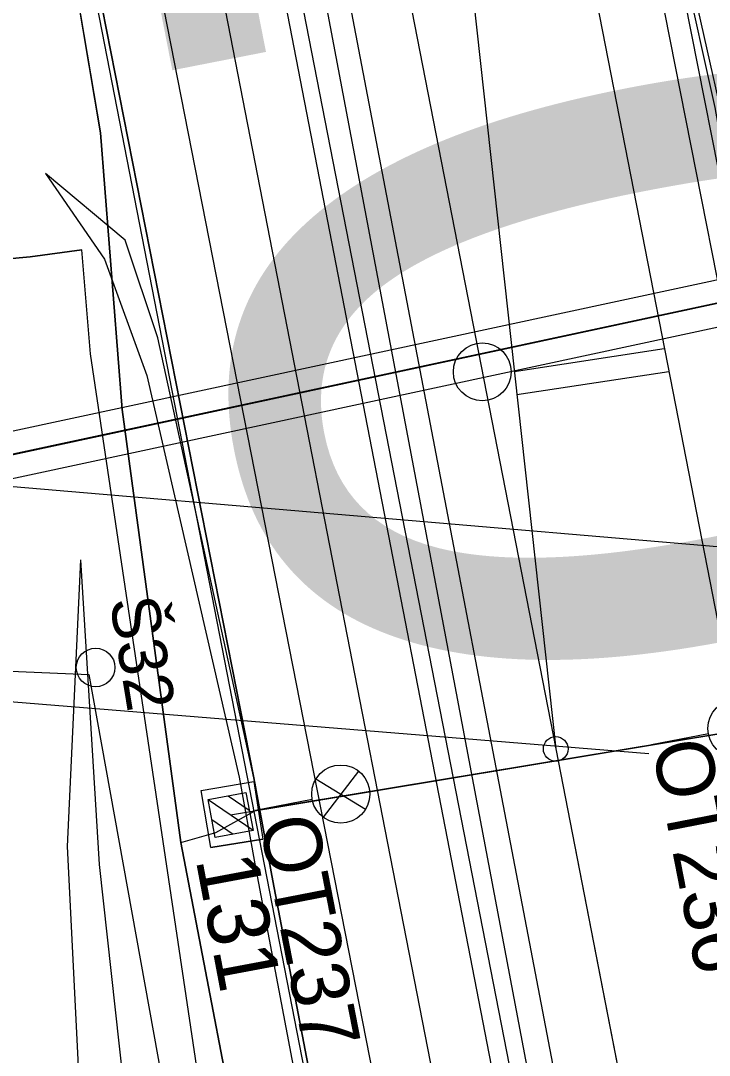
# Model space of a CAD drawing. Extents: x -545846 to -545044, y -1122650 to -1119108.
# Drawn here: x -545656.67 to -545638.82, y -1119592.1 to -1119565.28 of the extents above; entities that cross this region are included whole.
import ezdxf

# ---------------------------------------------------------------- set-up
doc = ezdxf.new("R2010")
doc.units = 0
for name, color, linetype in [('osvětlené plochy-hodnota-obrys', 7, 'Continuous'), ('Vrstva 1 - Koleje', 7, 'Continuous'), ('Vrstva 11 - Trakce', 7, 'Continuous'), ('Vrstva 12 - Trakce zaklady', 7, 'Continuous'), ('Vrstva 19', 7, 'Continuous'), ('Vrstva 19 - Staniceni', 7, 'Continuous'), ('Vrstva 2 - Vyhybky', 7, 'Continuous'), ('Vrstva 25', 7, 'Continuous'), ('Vrstva 26', 7, 'Continuous'), ('Vrstva 28 - zabzar', 7, 'Continuous'), ('Vrstva 31', 7, 'Continuous'), ('Vrstva 32', 7, 'Continuous'), ('Vrstva 35', 7, 'Continuous'), ('Vrstva 4 - Teren - stezky - prechody - plochy', 7, 'Continuous'), ('Vrstva 43', 7, 'Continuous'), ('Vrstva 44', 7, 'Continuous'), ('Vrstva 49', 7, 'Continuous'), ('Vrstva 63', 7, 'Continuous'), ('Vrstva 7 - Namezniky-vystroj', 7, 'Continuous')]:
    doc.layers.add(name, color=color, linetype=linetype)

msp = doc.modelspace()

# ---------------------------------------------------------------- linework, layer by layer
at = {"layer": 'osvětlené plochy-hodnota-obrys'}
for points in [[(-545716.386, -1119223.717), (-545705.994, -1119221.66), (-545669.439, -1119408.759), (-545659.4, -1119462.635), (-545647.69, -1119521.347), (-545640.519, -1119558.729), (-545633.585, -1119589.698), (-545629.517, -1119613.814), (-545623.042, -1119645.057), (-545619.034, -1119667.556), (-545607.519, -1119727.517)], [(-545610.895, -1119760.665), (-545622.836, -1119699.488), (-545637.26, -1119626.872), (-545653.542, -1119543.449), (-545716.386, -1119223.717)], [(-545618.794, -1119749.17), (-545664.282, -1119515.639)]]:
    msp.add_lwpolyline(points, dxfattribs=at)
at = {"layer": 'Vrstva 1 - Koleje'}
for points in [[(-545670.736, -1119486.005), (-545668.403, -1119493.448), (-545665.355, -1119503.63), (-545662.43, -1119514.19), (-545659.814, -1119524.462), (-545657.519, -1119534.337), (-545655.38, -1119544.464), (-545653.502, -1119554.064), (-545651.433, -1119564.675), (-545649.38, -1119575.204), (-545647.23, -1119586.243), (-545645.16, -1119596.868), (-545643.254, -1119606.626), (-545640.837, -1119619.032)], [(-545661.358, -1119488.941), (-545659.379, -1119499.086), (-545658.213, -1119505.075), (-545656.26, -1119515.094), (-545654.191, -1119525.718), (-545653.022, -1119531.715), (-545652.764, -1119533.036), (-545651.421, -1119539.927), (-545649.507, -1119549.759), (-545647.011, -1119562.533), (-545642.802, -1119584.154), (-545639.767, -1119599.744), (-545638.981, -1119603.782), (-545638.828, -1119604.567)], [(-545653.037, -1119506.841), (-545652.888, -1119507.607), (-545649.059, -1119527.252), (-545646.668, -1119549.037), (-545645.204, -1119562.292), (-545642.802, -1119584.154), (-545638.981, -1119603.782), (-545638.828, -1119604.567)], [(-545653.037, -1119506.841), (-545652.888, -1119507.607), (-545652.099, -1119511.657), (-545649.059, -1119527.252), (-545644.851, -1119548.835), (-545643.914, -1119553.655), (-545642.404, -1119561.39), (-545639.909, -1119574.181), (-545637.584, -1119586.095), (-545635.82, -1119595.156), (-545633.965, -1119604.658), (-545632.137, -1119614.029), (-545631.264, -1119618.51), (-545629.612, -1119626.967), (-545629.361, -1119628.256), (-545628.203, -1119634.204), (-545626.651, -1119642.2), (-545624.573, -1119652.836), (-545622.753, -1119662.157), (-545621.579, -1119668.177), (-545619.497, -1119678.862), (-545617.408, -1119689.578), (-545615.292, -1119700.416), (-545613.256, -1119710.876)]]:
    msp.add_lwpolyline(points, dxfattribs=at)
at = {"layer": 'Vrstva 11 - Trakce'}
for p, q in [((-545624.576, -1119581.445), (-545651.228, -1119585.868)), ((-545651.809, -1119585.468), (-545650.645, -1119586.264)), ((-545651.288, -1119585.371), (-545650.743, -1119585.743)), ((-545651.714, -1119585.987), (-545651.162, -1119586.364))]:
    msp.add_line(p, q, dxfattribs=at)
msp.add_lwpolyline([(-545650.829, -1119585.284), (-545650.644, -1119586.267), (-545651.627, -1119586.452), (-545651.812, -1119585.469)], close=True, dxfattribs=at)
at = {"layer": 'Vrstva 12 - Trakce zaklady'}
for p, q in [((-545650.63, -1119585.002), (-545650.396, -1119586.492)), ((-545651.741, -1119586.707), (-545651.988, -1119585.228))]:
    msp.add_line(p, q, dxfattribs=at)
for points in [[(-545650.63, -1119585.002), (-545650.396, -1119586.492), (-545651.741, -1119586.707), (-545651.988, -1119585.228), (-545650.63, -1119585.002)], [(-545651.988, -1119585.228), (-545651.988, -1119585.228), (-545650.63, -1119585.002), (-545650.63, -1119585.002)], [(-545651.741, -1119586.707), (-545651.741, -1119586.707), (-545650.396, -1119586.492), (-545650.396, -1119586.492)]]:
    msp.add_lwpolyline(points, dxfattribs=at)
at = {"layer": 'Vrstva 19'}
for points in [[(-545664.878, -1119577.632), (-545626.84, -1119569.462)], [(-545664.746, -1119578.217), (-545626.701, -1119570.045)], [(-545626.702, -1119570.04), (-545663.566, -1119577.951)], [(-545664.614, -1119578.802), (-545626.561, -1119570.628)]]:
    msp.add_lwpolyline(points, dxfattribs=at)
at = {"layer": 'Vrstva 19 - Staniceni'}
msp.add_circle((-545644.705, -1119574.38), 0.75, dxfattribs=at)
at = {"layer": 'Vrstva 2 - Vyhybky'}
for points in [[(-545645.204, -1119562.292), (-545642.802, -1119584.154)], [(-545647.011, -1119562.533), (-545642.802, -1119584.154), (-545638.981, -1119603.782), (-545638.828, -1119604.567)]]:
    msp.add_lwpolyline(points, dxfattribs=at)
msp.add_circle((-545642.802, -1119584.154), 0.32, dxfattribs=at)
at = {"layer": 'Vrstva 25'}
for p, q in [((-545638.845, -1119583.765), (-545640.317, -1119584.052)), ((-545647.913, -1119584.727), (-545648.826, -1119585.926)), ((-545647.734, -1119585.727), (-545649.018, -1119584.935)), ((-545649.113, -1119585.467), (-545650.585, -1119585.754))]:
    msp.add_line(p, q, dxfattribs=at)
msp.add_lwpolyline([(-545624.576, -1119581.445), (-545650.585, -1119585.754)], dxfattribs=at)
for centre in [(-545638.104, -1119583.623), (-545648.372, -1119585.325)]:
    msp.add_circle(centre, 0.754, dxfattribs=at)
at = {"layer": 'Vrstva 26'}
for points in [[(-545648.815, -1119598.781), (-545650.646, -1119596.363), (-545652.517, -1119586.577), (-545654.036, -1119575.352), (-545654.599, -1119568.181), (-545656.827, -1119554.929), (-545656.997, -1119554.007), (-545657.467, -1119552.439), (-545664.456, -1119553.497), (-545667.067, -1119553.592), (-545667.602, -1119550.556), (-545667.729, -1119548.937), (-545668.467, -1119543.92), (-545670.355, -1119535.438), (-545673.845, -1119519.482), (-545676.203, -1119508.264), (-545678.142, -1119500.554), (-545680.197, -1119492.738), (-545680.794, -1119490.021), (-545681.126, -1119488.142)], [(-545652.517, -1119586.577), (-545651.612, -1119586.323), (-545650.585, -1119585.754)]]:
    msp.add_lwpolyline(points, dxfattribs=at)
at = {"layer": 'Vrstva 28 - zabzar'}
for points in [[(-545629.8, -1119612.08), (-545631.93, -1119600), (-545634.62, -1119586.79), (-545636.82, -1119576.2), (-545637.62, -1119573.41), (-545638.67, -1119567.53), (-545639.49, -1119563.82), (-545639.85, -1119560.18), (-545641.01, -1119554.98), (-545644.07, -1119538.51), (-545646.66, -1119527.22), (-545647.144, -1119525.532), (-545647.46, -1119524.27), (-545648.47, -1119517.64), (-545649.03, -1119512.55), (-545649.84, -1119510.97), (-545650.5, -1119507.69), (-545650.68, -1119506.85), (-545651.64, -1119501.97), (-545654.86, -1119485.39)], [(-545649.855, -1119599.344), (-545650.84, -1119597.26), (-545651.93, -1119593.57), (-545654.86, -1119573.91), (-545655.08, -1119571.22), (-545656.42, -1119571.4), (-545660, -1119571.73), (-545661.56, -1119571.75), (-545664.78, -1119571.8), (-545665.2, -1119565.97), (-545667.1, -1119556.02), (-545671.77, -1119534.36), (-545673.21, -1119527.51), (-545675.52, -1119518.42), (-545676.6, -1119512.93), (-545677.33, -1119506.78), (-545681.37, -1119492.78), (-545681.68, -1119491.62), (-545683.99, -1119485.87)]]:
    msp.add_lwpolyline(points, dxfattribs=at)
at = {"layer": 'Vrstva 31'}
for points in [[(-545649.855, -1119599.344), (-545650.84, -1119597.26), (-545651.93, -1119593.57), (-545654.86, -1119573.91), (-545655.08, -1119571.22), (-545656.42, -1119571.4), (-545660, -1119571.73), (-545661.56, -1119571.75), (-545664.78, -1119571.8), (-545665.2, -1119565.97), (-545667.1, -1119556.02), (-545671.77, -1119534.36), (-545673.21, -1119527.51), (-545675.52, -1119518.42), (-545676.6, -1119512.93), (-545677.33, -1119506.78), (-545681.37, -1119492.78), (-545681.68, -1119491.62), (-545683.99, -1119485.87)], [(-545681.126, -1119488.142), (-545680.197, -1119492.738), (-545678.775, -1119498.148), (-545676.203, -1119508.264), (-545673.845, -1119519.482), (-545670.355, -1119535.438), (-545668.467, -1119543.92), (-545667.729, -1119548.937), (-545667.602, -1119550.556), (-545667.067, -1119553.592), (-545664.456, -1119553.497), (-545660.52, -1119553.11), (-545657.91, -1119552.94), (-545656.997, -1119554.007), (-545654.599, -1119568.181), (-545654.036, -1119575.352), (-545652.517, -1119586.577), (-545650.646, -1119596.363), (-545648.815, -1119598.781)], [(-545648.815, -1119598.781), (-545650.646, -1119596.363), (-545652.517, -1119586.577), (-545654.036, -1119575.352), (-545654.599, -1119568.181), (-545656.827, -1119554.929), (-545656.997, -1119554.007), (-545657.91, -1119552.94), (-545660.52, -1119553.11), (-545664.456, -1119553.497)]]:
    msp.add_lwpolyline(points, dxfattribs=at)
at = {"layer": 'Vrstva 32'}
msp.add_lwpolyline([(-545649.855, -1119599.344), (-545650.84, -1119597.26), (-545651.93, -1119593.57), (-545654.86, -1119573.91), (-545655.08, -1119571.22), (-545656.42, -1119571.4), (-545660, -1119571.73), (-545661.56, -1119571.75), (-545664.78, -1119571.8), (-545665.2, -1119565.97), (-545667.1, -1119556.02), (-545671.77, -1119534.36), (-545673.21, -1119527.51), (-545675.52, -1119518.42), (-545676.6, -1119512.93), (-545677.33, -1119506.78), (-545681.37, -1119492.78), (-545681.68, -1119491.62), (-545683.99, -1119485.87)], dxfattribs=at)
at = {"layer": 'Vrstva 35'}
msp.add_lwpolyline([(-545661.56, -1119571.75), (-545660, -1119571.73), (-545656.42, -1119571.4), (-545655.08, -1119571.22)], dxfattribs=at)
at = {"layer": 'Vrstva 4 - Teren - stezky - prechody - plochy'}
for points in [[(-545628.853, -1119622.763), (-545638.621, -1119571.934), (-545645.785, -1119535.614), (-545651.795, -1119505.293), (-545654.152, -1119492.935)], [(-545650.63, -1119584.9), (-545657.369, -1119550.681), (-545660.463, -1119535.199), (-545664.169, -1119519.775), (-545667.149, -1119508.296), (-545669.067, -1119499.733), (-545669.306, -1119498.975), (-545668.362, -1119498.706), (-545661.426, -1119496.568), (-545661.835, -1119494.163), (-545658.883, -1119493.553)], [(-545630.993, -1119656.823), (-545632.27, -1119648.758), (-545633.986, -1119638.317), (-545635.874, -1119627.618), (-545641.206, -1119601.036), (-545648.737, -1119561.68), (-545660.263, -1119502.835), (-545661.421, -1119496.666)], [(-545630.993, -1119656.823), (-545631.879, -1119657.017), (-545637.587, -1119627.431), (-545642.784, -1119601.05), (-545650.341, -1119562.037), (-545654.864, -1119538.891), (-545658.993, -1119521.274), (-545660.867, -1119513.982), (-545663.726, -1119503.551), (-545665.454, -1119497.849)], [(-545668.116, -1119499.514), (-545669.067, -1119499.733), (-545667.149, -1119508.296), (-545664.169, -1119519.775), (-545660.463, -1119535.199), (-545657.369, -1119550.681), (-545650.63, -1119584.9), (-545650.137, -1119587.57), (-545643.597, -1119621.824), (-545639.676, -1119641.733), (-545638.648, -1119646.558), (-545637.372, -1119653.536), (-545637.393, -1119653.539), (-545632.884, -1119675.451), (-545627.579, -1119703.177), (-545627.31, -1119704.719), (-545625.835, -1119712.063)], [(-545668.116, -1119499.514), (-545665.721, -1119507.929), (-545662.615, -1119519.622), (-545659.148, -1119534.332), (-545655.765, -1119550.675), (-545641.939, -1119621.169), (-545637.993, -1119641.248), (-545631.568, -1119675.037), (-545626.43, -1119701.616), (-545620.933, -1119729.23), (-545619.776, -1119736.256), (-545618.414, -1119746.042), (-545618.118, -1119750.155), (-545617.307, -1119763.323), (-545616.619, -1119772.592), (-545616.223, -1119779.957), (-545616.135, -1119786.617)], [(-545656.026, -1119569.241), (-545654.499, -1119571.456), (-545653.398, -1119574.472), (-545651.008, -1119584.887), (-545650.604, -1119587.134), (-545647.381, -1119604.145), (-545643.83, -1119621.835), (-545639.676, -1119641.733)], [(-545639.676, -1119641.733), (-545643.597, -1119621.824), (-545650.137, -1119587.57), (-545650.63, -1119584.9), (-545653.11, -1119573.498), (-545653.963, -1119570.966), (-545656.026, -1119569.241)]]:
    msp.add_lwpolyline(points, dxfattribs=at)
at = {"layer": 'Vrstva 43'}
msp.add_circle((-545654.727, -1119582.043), 0.5, dxfattribs=at)
at = {"layer": 'Vrstva 44'}
for points in [[(-545686.717, -1119457.756), (-545678.249, -1119507.566), (-545678.197, -1119507.823), (-545678.143, -1119508.088), (-545669.049, -1119560.603), (-545668.972, -1119560.768), (-545669.024, -1119561.029), (-545669.819, -1119580.622), (-545669.63, -1119581.188), (-545669.088, -1119581.415), (-545665.555, -1119581.767), (-545664.442, -1119581.821), (-545654.9, -1119582.222)], [(-545622.746, -1119648.835), (-545632.623, -1119599.24), (-545640.335, -1119560.272)], [(-545632.322, -1119650.948), (-545641.9, -1119601.074), (-545649.267, -1119562.096), (-545649.25, -1119561.916)], [(-545654.9, -1119582.222), (-545645.965, -1119631.818), (-545637.145, -1119681.816), (-545629.836, -1119730.566), (-545626.416, -1119761.521), (-545622.849, -1119813.009), (-545619.592, -1119863.304), (-545618.858, -1119914.175), (-545618.881, -1119950.565), (-545618.715, -1119963.415), (-545629.02, -1119997.179)]]:
    msp.add_lwpolyline(points, dxfattribs=at)
at = {"layer": 'Vrstva 49'}
for points in [[(-545655.117, -1119579.257), (-545655.465, -1119586.681), (-545654.728, -1119601.362), (-545652.589, -1119621.359), (-545650.163, -1119640.071), (-545647.474, -1119659.033), (-545644.608, -1119679.124), (-545643.003, -1119694.436)], [(-545655.117, -1119579.257), (-545654.637, -1119587.147), (-545653.079, -1119601.278), (-545650.95, -1119621.407), (-545647.998, -1119639.764), (-545644.487, -1119662.372), (-545641.063, -1119679.985), (-545638.92, -1119699.386)]]:
    msp.add_lwpolyline(points, dxfattribs=at)
at = {"layer": 'Vrstva 63'}
for p, q in [((-545588.032, -1119583.243), (-545688.629, -1119574.644)), ((-545640.39, -1119584.279), (-545688.807, -1119580.348))]:
    msp.add_line(p, q, dxfattribs=at)
at = {"layer": 'Vrstva 7 - Namezniky-vystroj'}
for p, q in [((-545643.877, -1119574.37), (-545639.988, -1119573.778)), ((-545643.811, -1119574.967), (-545639.873, -1119574.368))]:
    msp.add_line(p, q, dxfattribs=at)

# ---------------------------------------------------------------- texts
at = {"layer": 'osvětlené plochy-hodnota-obrys'}
msp.add_text('20', height=22.7812, rotation=281.0956, dxfattribs=at).set_placement((-545655.704, -1119551.441))
at = {"layer": 'Vrstva 11 - Trakce'}
msp.add_text('131', height=1.6, rotation=280.644, dxfattribs=at).set_placement((-545652.136, -1119587.016))
at = {"layer": 'Vrstva 25'}
for s, rotation, p in [('OT236', 281.0424, (-545640.317, -1119584.052)), ('OT237', 281.0212, (-545650.491, -1119586.016))]:
    msp.add_text(s, height=1.5, rotation=rotation, dxfattribs=at).set_placement(p)
at = {"layer": 'Vrstva 43'}
msp.add_text('Š32', height=1.25, rotation=279.317, dxfattribs=at).set_placement((-545654.367, -1119580.297))

doc.saveas('drawing.dxf')
